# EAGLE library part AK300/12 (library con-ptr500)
CONNECTOR
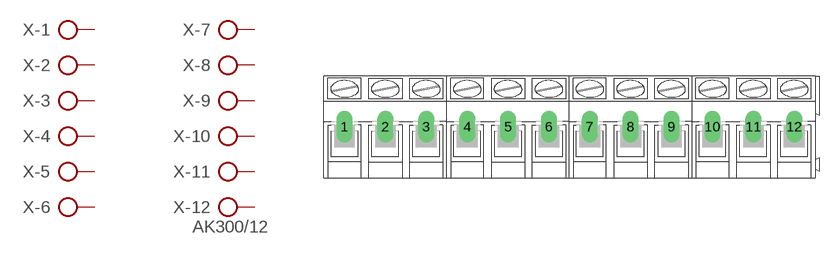
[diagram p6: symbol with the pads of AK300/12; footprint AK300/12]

Designator prefix X; gates -1=KL -2=KL -3=KL -4=KL -5=KL -6=KL -7=KL -8=KL -9=KL -10=KL -11=KL -12=KLV

## AK300/12 (OC_FARNELL: unknown; OC_NEWARK: unknown)  [AK300/12]
1  -1:KL  pas
2  -2:KL  pas
3  -3:KL  pas
4  -4:KL  pas
5  -5:KL  pas
6  -6:KL  pas
7  -7:KL  pas
8  -8:KL  pas
9  -9:KL  pas
10  -10:KL  pas
11  -11:KL  pas
12  -12:KL  pas

## Footprint AK300/12 (pad centres in mm)
CONNECTOR
drill 1.321 long: 1 -27.508,0; 2 -22.504,0; 3 -17.501,0; 4 -12.497,0; 5 -7.493,0; 6 -2.489,0; 7 2.489,0; 8 7.493,0; 9 12.497,0; 10 17.501,0; 11 22.504,0; 12 27.508,0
